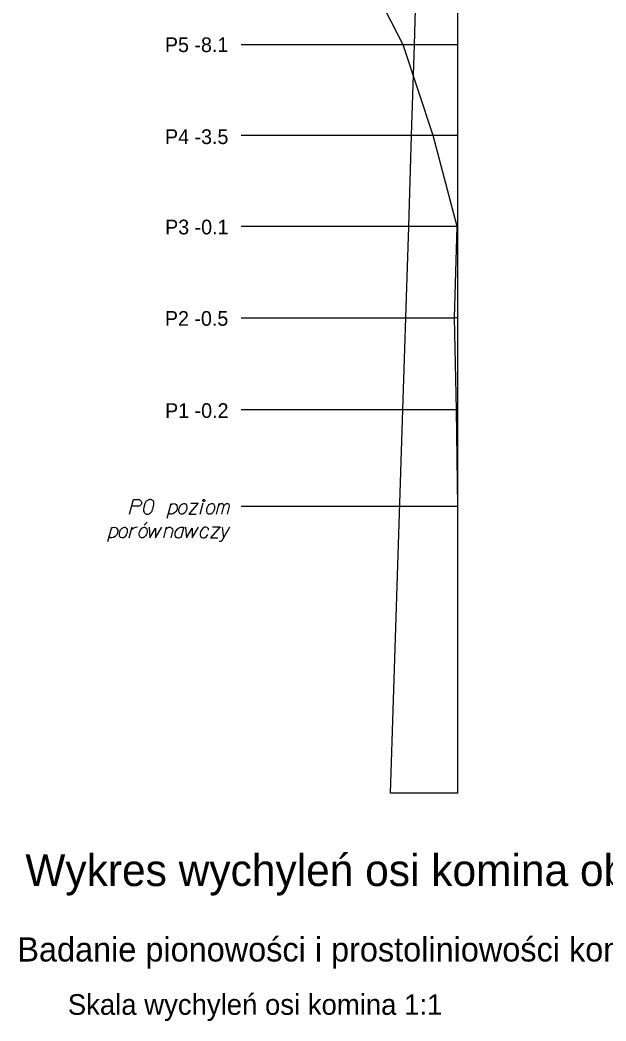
# Model space of a CAD drawing. Extents: x 138 to 264, y -75 to 121.
# Drawn here: x 229.14 to 237.9, y 84.56 to 99.53 of the extents above; entities that cross this region are included whole.
import ezdxf

# ---------------------------------------------------------------- set-up
doc = ezdxf.new("R2010")
doc.units = 0
for name, color, linetype in [('Opisy', 7, 'Continuous'), ('Standart wykresów', 7, 'Continuous'), ('Wykresy 4 maj 2008', 7, 'Continuous')]:
    doc.layers.add(name, color=color, linetype=linetype)

msp = doc.modelspace()

# ---------------------------------------------------------------- linework, layer by layer
at = {"layer": 'Standart wykresów'}
for p, q in [((235.685, 87.967), (235.685, 108.051)), ((235.038, 99.158), (235.083, 100.549)), ((234.872, 99.158), (232.448, 99.158)), ((234.996, 97.799), (235.038, 99.158)), ((235.319, 97.799), (232.448, 97.799)), ((234.953, 96.441), (234.996, 97.799)), ((235.677, 96.441), (232.448, 96.441)), ((234.911, 95.074), (234.953, 96.441)), ((235.685, 96.441), (235.677, 96.441)), ((232.448, 95.074), (235.639, 95.074)), ((234.866, 93.698), (234.911, 95.074)), ((235.666, 93.698), (232.448, 93.698)), ((234.679, 87.967), (234.866, 93.698)), ((235.685, 92.253), (232.448, 92.253)), ((235.685, 87.967), (234.679, 87.967))]:
    msp.add_line(p, q, dxfattribs=at)
for points in [[(230.774, 92.137), (230.833, 92.357), (230.908, 92.357), (230.918, 92.355), (230.923, 92.354), (230.934, 92.348), (230.94, 92.343), (230.946, 92.336), (230.951, 92.328), (230.954, 92.316), (230.956, 92.305), (230.954, 92.296), (230.953, 92.29), (230.949, 92.283), (230.946, 92.277), (230.94, 92.271), (230.934, 92.265), (230.928, 92.262), (230.92, 92.258), (230.911, 92.257), (230.807, 92.257)], [(231.089, 92.357), (231.086, 92.357), (231.076, 92.355), (231.069, 92.354), (231.063, 92.352), (231.055, 92.348), (231.044, 92.343), (231.036, 92.338), (231.027, 92.331), (231.022, 92.324), (231.017, 92.316), (231.012, 92.307), (231.006, 92.296), (231.003, 92.29), (230.999, 92.279), (230.994, 92.262), (230.989, 92.236), (230.986, 92.215), (230.986, 92.196), (230.987, 92.182), (230.994, 92.167), (230.999, 92.158), (231.008, 92.148), (231.018, 92.141), (231.024, 92.139), (231.034, 92.137), (231.043, 92.137), (231.057, 92.139), (231.069, 92.142), (231.077, 92.148), (231.089, 92.156), (231.095, 92.161), (231.102, 92.168), (231.107, 92.175), (231.11, 92.18), (231.114, 92.189), (231.115, 92.193), (231.119, 92.201), (231.122, 92.212), (231.126, 92.222), (231.128, 92.229), (231.129, 92.234), (231.131, 92.241), (231.135, 92.257), (231.136, 92.265), (231.138, 92.274), (231.14, 92.286), (231.141, 92.302), (231.141, 92.307), (231.14, 92.314), (231.138, 92.321), (231.133, 92.331), (231.128, 92.338), (231.122, 92.343), (231.115, 92.348), (231.109, 92.352), (231.103, 92.354), (231.098, 92.355), (231.089, 92.357)], [(231.341, 92.08), (231.4, 92.296)], [(231.394, 92.277), (231.412, 92.291), (231.438, 92.296), (231.458, 92.293), (231.472, 92.283), (231.483, 92.269), (231.49, 92.25), (231.491, 92.232), (231.488, 92.217), (231.483, 92.198), (231.469, 92.177), (231.451, 92.158), (231.425, 92.141), (231.403, 92.137), (231.382, 92.139), (231.36, 92.151)], [(231.588, 92.296), (231.6, 92.296), (231.614, 92.29), (231.628, 92.271), (231.63, 92.262), (231.632, 92.253), (231.632, 92.246), (231.632, 92.22), (231.626, 92.203), (231.618, 92.182), (231.607, 92.165), (231.59, 92.149), (231.574, 92.137), (231.548, 92.137), (231.538, 92.141), (231.528, 92.149), (231.522, 92.158), (231.516, 92.179), (231.516, 92.21), (231.519, 92.22), (231.526, 92.243), (231.533, 92.255), (231.536, 92.262), (231.554, 92.281), (231.571, 92.291), (231.588, 92.296)], [(231.692, 92.3), (231.805, 92.3), (231.661, 92.137), (231.772, 92.137)], [(231.834, 92.137), (231.879, 92.305)], [(231.883, 92.357), (231.891, 92.357), (231.897, 92.354), (231.902, 92.347), (231.902, 92.338), (231.897, 92.331), (231.891, 92.328), (231.883, 92.328), (231.878, 92.331), (231.872, 92.338), (231.872, 92.347), (231.878, 92.354), (231.883, 92.357)], [(232.004, 92.296), (232.016, 92.296), (232.03, 92.29), (232.044, 92.271), (232.046, 92.262), (232.047, 92.253), (232.047, 92.246), (232.047, 92.22), (232.042, 92.203), (232.033, 92.182), (232.023, 92.165), (232.006, 92.149), (231.99, 92.137), (231.964, 92.137), (231.954, 92.141), (231.943, 92.149), (231.938, 92.158), (231.931, 92.179), (231.931, 92.21), (231.935, 92.22), (231.942, 92.243), (231.949, 92.255), (231.952, 92.262), (231.969, 92.281), (231.987, 92.291), (232.004, 92.296)], [(232.077, 92.137), (232.117, 92.295)], [(232.106, 92.253), (232.115, 92.272), (232.124, 92.283), (232.134, 92.29), (232.144, 92.295), (232.151, 92.298), (232.162, 92.298), (232.165, 92.296), (232.172, 92.29), (232.179, 92.281), (232.184, 92.265), (232.186, 92.257), (232.195, 92.272), (232.205, 92.283), (232.215, 92.29), (232.226, 92.295), (232.234, 92.298), (232.243, 92.298), (232.25, 92.296), (232.255, 92.29), (232.26, 92.281), (232.266, 92.265), (232.267, 92.257), (232.238, 92.137)], [(232.156, 92.137), (232.186, 92.257)], [(230.451, 91.727), (230.51, 91.943)], [(230.505, 91.924), (230.522, 91.938), (230.548, 91.943), (230.569, 91.94), (230.583, 91.929), (230.593, 91.916), (230.6, 91.897), (230.602, 91.879), (230.598, 91.864), (230.593, 91.845), (230.579, 91.824), (230.562, 91.805), (230.536, 91.787), (230.513, 91.784), (230.493, 91.786), (230.47, 91.798)], [(230.699, 91.943), (230.711, 91.943), (230.725, 91.936), (230.739, 91.917), (230.74, 91.909), (230.742, 91.9), (230.742, 91.893), (230.742, 91.867), (230.737, 91.85), (230.728, 91.829), (230.718, 91.812), (230.7, 91.796), (230.685, 91.784), (230.659, 91.784), (230.648, 91.787), (230.638, 91.796), (230.633, 91.805), (230.626, 91.825), (230.626, 91.857), (230.629, 91.867), (230.636, 91.89), (230.643, 91.902), (230.647, 91.909), (230.664, 91.928), (230.681, 91.938), (230.699, 91.943)], [(230.771, 91.784), (230.815, 91.948)], [(230.804, 91.909), (230.813, 91.916), (230.832, 91.929), (230.853, 91.938), (230.868, 91.943), (230.893, 91.948)], [(230.995, 91.943), (231.007, 91.943), (231.021, 91.936), (231.035, 91.917), (231.036, 91.909), (231.038, 91.9), (231.038, 91.893), (231.038, 91.867), (231.033, 91.85), (231.024, 91.829), (231.014, 91.812), (230.997, 91.796), (230.981, 91.784), (230.955, 91.784), (230.945, 91.787), (230.934, 91.796), (230.929, 91.805), (230.922, 91.825), (230.922, 91.857), (230.926, 91.867), (230.933, 91.89), (230.939, 91.902), (230.943, 91.909), (230.96, 91.928), (230.978, 91.938), (230.995, 91.943)], [(231.038, 92.02), (230.995, 91.971)], [(231.068, 91.942), (231.081, 91.784), (231.165, 91.928), (231.166, 91.784), (231.258, 91.945)], [(231.288, 91.784), (231.331, 91.943)], [(231.321, 91.905), (231.326, 91.914), (231.333, 91.924), (231.338, 91.929), (231.345, 91.936), (231.352, 91.94), (231.36, 91.943), (231.369, 91.945), (231.376, 91.945), (231.385, 91.943), (231.392, 91.94), (231.398, 91.936), (231.405, 91.931), (231.412, 91.924), (231.416, 91.919), (231.419, 91.912), (231.423, 91.903), (231.392, 91.784)], [(231.582, 91.929), (231.57, 91.938), (231.541, 91.938), (231.523, 91.935), (231.492, 91.917), (231.466, 91.886), (231.454, 91.853), (231.452, 91.836), (231.454, 91.822), (231.459, 91.81), (231.47, 91.796), (231.482, 91.787), (231.501, 91.784), (231.515, 91.786), (231.528, 91.787), (231.547, 91.798)], [(231.586, 91.943), (231.544, 91.784)], [(231.615, 91.942), (231.629, 91.784), (231.712, 91.928), (231.714, 91.784), (231.806, 91.945)], [(231.958, 91.897), (231.956, 91.917), (231.948, 91.931), (231.937, 91.938), (231.916, 91.942), (231.897, 91.942), (231.873, 91.926), (231.854, 91.9), (231.84, 91.874), (231.835, 91.855), (231.835, 91.825), (231.837, 91.815), (231.844, 91.801), (231.859, 91.787), (231.877, 91.784), (231.896, 91.786), (231.906, 91.789), (231.929, 91.805), (231.946, 91.834)], [(232.019, 91.947), (232.131, 91.947), (231.987, 91.784), (232.098, 91.784)], [(232.272, 91.945), (232.183, 91.784), (232.155, 91.737), (232.149, 91.734), (232.14, 91.73), (232.123, 91.727), (232.116, 91.727)], [(232.161, 91.943), (232.183, 91.784)]]:
    msp.add_lwpolyline(points, dxfattribs=at)
at = {"layer": 'Wykresy 4 maj 2008'}
for p, q in [((235.685, 99.158), (234.872, 99.158)), ((235.685, 97.799), (235.319, 97.799)), ((235.685, 95.074), (235.639, 95.074)), ((235.685, 93.698), (235.666, 93.698))]:
    msp.add_line(p, q, dxfattribs=at)
msp.add_lwpolyline([(235.685, 92.253), (235.666, 93.698), (235.639, 95.074), (235.677, 96.441), (235.319, 97.799), (234.872, 99.158), (234.156, 100.549), (233.07, 101.951), (233.567, 102.945), (233.344, 103.925), (233.777, 104.384), (234.265, 104.901), (234.83, 105.369), (235.733, 105.937), (237.534, 106.463), (237.155, 106.65), (241.683, 107.348), (244.665, 107.711), (246.042, 107.967)], dxfattribs=at)

# ---------------------------------------------------------------- texts
at = {"layer": 'Opisy'}
for s, height, p in [('Wykres wychyleń osi komina obserwowanych ze stanowiska 1002', 0.47516, (229.217, 86.577)), ('Badanie pionowości i prostoliniowości komina zakładu ceramicznego "Ceramika Stróże"', 0.36281, (229.098, 85.448)), ('Skala wychyleń osi komina 1:1', 0.30766, (229.853, 84.651))]:
    msp.add_text(s, height=height, dxfattribs=at).set_placement(p)
at = {"layer": 'Wykresy 4 maj 2008'}
for s, p in [('P5 -8.1', (231.305, 99.048)), ('P4 -3.5', (231.307, 97.673)), ('P3 -0.1', (231.308, 96.322)), ('P2 -0.5', (231.305, 94.955)), ('P1 -0.2', (231.308, 93.577))]:
    msp.add_text(s, height=0.22, dxfattribs=at).set_placement(p)

doc.saveas('drawing.dxf')
